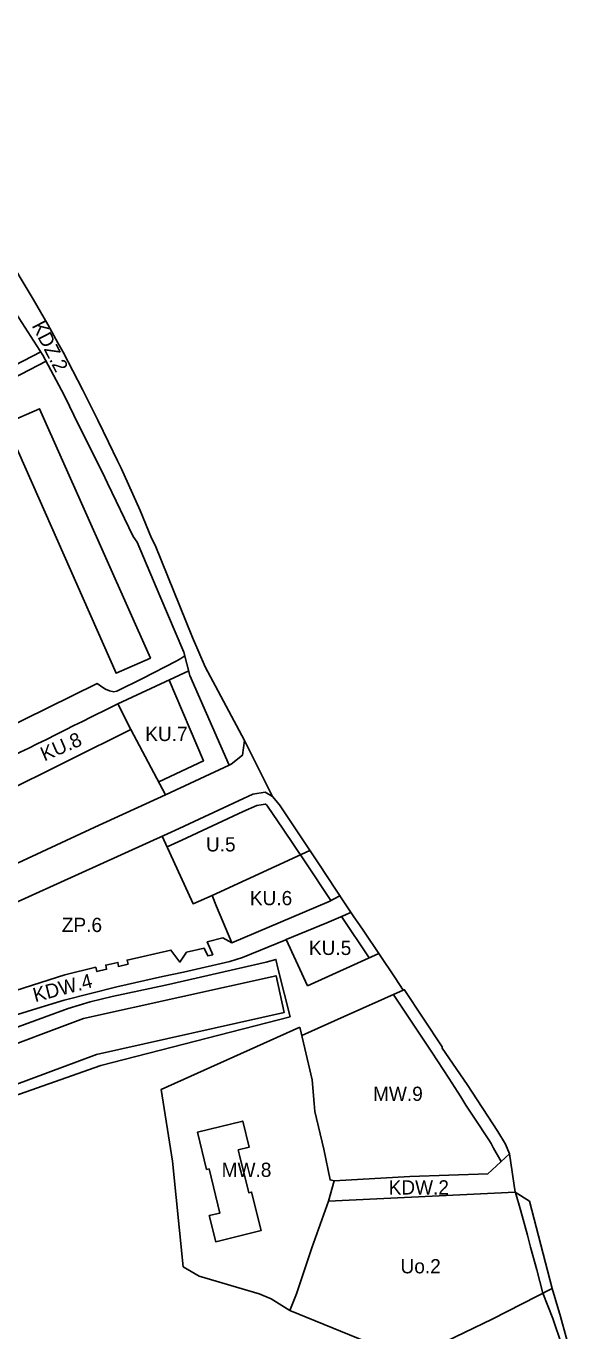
# Model space of a CAD drawing. Extents: x 7426178 to 7427732, y 5548847 to 5550287.
# Drawn here: x 7427225.9 to 7427398.2, y 5549279.8 to 5549692.3 of the extents above; entities that cross this region are included whole.
import ezdxf

# ---------------------------------------------------------------- set-up
doc = ezdxf.new("R2010")
doc.units = 0
for name, color, linetype in [('linie_rozgraniczajace', 7, 'Continuous'), ('linie_zabudowy_nieprzekraczalne', 7, 'Continuous'), ('linie_zabudowy_obowiazujace', 7, 'Continuous'), ('oznaczenia_przeznaczen', 7, 'Continuous')]:
    doc.layers.add(name, color=color, linetype=linetype)

msp = doc.modelspace()

# ---------------------------------------------------------------- linework, layer by layer
at = {"layer": 'linie_rozgraniczajace'}
for p, q in [((7427228.13, 5549605.99), (7427219.14, 5549621.01)), ((7427237.55, 5549589.21), (7427235.91, 5549592.2)), ((7427243.64, 5549577.42), (7427237.55, 5549589.21)), ((7427248.55, 5549567.8), (7427243.64, 5549577.42)), ((7427303.71, 5549448.83), (7427294.86, 5549466.52)), ((7427305.89, 5549446.11), (7427303.71, 5549448.83)), ((7427318.5, 5549427.19), (7427305.89, 5549446.11)), ((7427284.57, 5549417.53), (7427315.49, 5549431.7)), ((7427326.25, 5549415.45), (7427318.5, 5549427.19)), ((7427329.32, 5549410.72), (7427326.25, 5549415.45)), ((7427331.18, 5549408.21), (7427329.32, 5549410.72)), ((7427314.78, 5549388.92), (7427308.04, 5549403.57)), ((7427314.78, 5549388.92), (7427337.24, 5549399.15)), ((7427344.92, 5549387.57), (7427342.4, 5549391.44)), ((7427309.23, 5549379.16), (7427309.23, 5549379.16)), ((7427357.25, 5549369.27), (7427357.31, 5549369.67)), ((7427365.12, 5549357.73), (7427357.25, 5549369.27)), ((7427374.86, 5549342.9), (7427365.12, 5549357.73)), ((7427380.29, 5549323.65), (7427378.49, 5549335.83)), ((7427321.33, 5549320.9), (7427323.15, 5549327.33)), ((7427321.33, 5549320.9), (7427380.29, 5549323.65)), ((7427394.66, 5549284.38), (7427392.05, 5549293.25)), ((7427398.23, 5549271.32), (7427394.66, 5549284.38))]:
    msp.add_line(p, q, dxfattribs=at)
for points in [[(7427172.45, 5549692.34), (7427176.9, 5549682.64), (7427185.66, 5549667.5), (7427192.62, 5549654.65), (7427196.91, 5549647.34), (7427207.1, 5549629.09), (7427213.58, 5549617.58), (7427221.64, 5549603.03), (7427231.15, 5549588.29), (7427237.07, 5549577.28), (7427238.15, 5549575.04), (7427242.34, 5549566.53), (7427249.94, 5549551.24), (7427251.6, 5549547.85), (7427259.67, 5549530.97), (7427260.96, 5549529.16), (7427268.09, 5549512.22), (7427275.65, 5549494.4), (7427277.61, 5549486.99), (7427289.94, 5549458.65)], [(7427230.48, 5549589.38), (7427148.85, 5549546.95), (7427088.25, 5549515.33), (7427086.86, 5549515.01), (7427085.02, 5549515.09), (7427083.04, 5549515.77), (7427081.79, 5549516.82), (7427081.29, 5549518.09), (7427073.92, 5549541.54), (7427073.78, 5549545.19), (7427074.5, 5549552.91), (7427080.17, 5549602.79), (7427080.47, 5549609.99), (7427078.8, 5549622.63), (7427076.71, 5549630.64), (7427074.28, 5549638.8)], [(7427235.91, 5549592.2), (7427232.71, 5549598.04), (7427228.13, 5549605.99)], [(7427115.22, 5549413.02), (7427108.83, 5549432.27), (7427108.83, 5549432.27), (7427092.63, 5549482.16), (7427086.13, 5549502.57), (7427086.04, 5549505.04), (7427086.55, 5549507.51), (7427087.93, 5549510.29), (7427089.87, 5549512.02), (7427150.51, 5549543.92), (7427232.16, 5549586.41)], [(7427254.76, 5549554.9), (7427251.91, 5549560.81), (7427248.55, 5549567.8)], [(7427266.6, 5549528.2), (7427265.5, 5549530.5), (7427261.87, 5549539.15), (7427255.84, 5549552.59), (7427254.76, 5549554.9)], [(7427294.86, 5549466.52), (7427282.38, 5549489.77), (7427278.39, 5549499.07), (7427266.6, 5549528.2)], [(7427217.26, 5549469.25), (7427248.33, 5549484.49), (7427250.12, 5549483.21), (7427250.95, 5549482.7), (7427252.21, 5549482.24), (7427253.54, 5549481.92), (7427254.54, 5549482.05), (7427262.59, 5549486.08), (7427273.25, 5549491.52), (7427274.75, 5549492.36), (7427275.95, 5549493.25)], [(7427294.86, 5549466.52), (7427294.18, 5549461.82), (7427290.62, 5549458.96), (7427289.94, 5549458.65), (7427269.86, 5549449.36), (7427258.91, 5549469.96), (7427254.85, 5549478.08), (7427277.21, 5549488.48)], [(7427254.85, 5549478.08), (7427251.88, 5549476.6), (7427246.33, 5549473.85), (7427243.64, 5549472.52), (7427240.95, 5549471.19), (7427238.26, 5549469.86), (7427235.39, 5549468.41), (7427232.25, 5549466.85), (7427229.34, 5549465.41), (7427226.67, 5549464.08), (7427223.99, 5549462.75), (7427221.31, 5549461.42), (7427218.63, 5549460.09), (7427215.71, 5549458.63)], [(7427258.91, 5549469.96), (7427239.47, 5549460.24), (7427236.31, 5549458.73), (7427219.73, 5549450.51), (7427215.71, 5549458.63)], [(7427270.54, 5549437.01), (7427274.23, 5549438.66), (7427292.9, 5549447.39), (7427297.47, 5549449.53), (7427301.41, 5549450.12), (7427303.71, 5549448.83)], [(7427172.51, 5549404.3), (7427192.72, 5549413.62), (7427247.52, 5549439.05), (7427269.86, 5549449.36)], [(7427191.99, 5549400.58), (7427193.09, 5549401.11), (7427192.87, 5549401.78), (7427270.54, 5549437.01)], [(7427268.84, 5549436.24), (7427278.59, 5549414.89), (7427284.57, 5549417.53), (7427285.94, 5549414.03), (7427290.85, 5549402.55), (7427288.04, 5549404.1), (7427283.09, 5549402.88), (7427284.81, 5549398.78), (7427283.21, 5549398.43), (7427282.09, 5549400.85), (7427276.53, 5549399.56), (7427274.41, 5549396.43), (7427271.57, 5549400.22), (7427257.74, 5549397.06), (7427258.05, 5549395.78), (7427255, 5549395.07), (7427254.86, 5549396.34), (7427251.01, 5549395.48), (7427251.26, 5549394.16), (7427248.21, 5549393.43), (7427247.83, 5549394.81), (7427238.13, 5549392.37), (7427214.65, 5549384.89)], [(7427290.85, 5549402.55), (7427321.54, 5549415.63), (7427324.98, 5549417.38)], [(7427307.84, 5549403.48), (7427308.04, 5549403.57), (7427320.84, 5549408.89), (7427326.75, 5549411.42), (7427328.1, 5549411.99), (7427328.43, 5549412.09)], [(7427342.4, 5549391.44), (7427332.51, 5549406.21), (7427331.18, 5549408.21)], [(7427307.84, 5549403.48), (7427294.24, 5549397.88), (7427290.18, 5549396.65), (7427275.57, 5549393.25), (7427268.93, 5549391.83), (7427254.5, 5549388.59), (7427237.89, 5549384.43), (7427229.28, 5549381.76), (7427206.45, 5549374.66), (7427194.14, 5549397.18)], [(7427208.1, 5549370.51), (7427214.58, 5549372.79), (7427231.65, 5549379.05), (7427239.19, 5549381.81), (7427246.05, 5549383.91), (7427253.06, 5549385.54), (7427269.91, 5549389.18), (7427301.72, 5549396.43), (7427304.78, 5549397.3), (7427305.44, 5549394.04)], [(7427309.23, 5549379.16), (7427305.44, 5549394.04)], [(7427312.9, 5549373.19), (7427326.3, 5549379.21), (7427344.92, 5549387.57)], [(7427357.31, 5549369.67), (7427345.31, 5549387.76), (7427344.92, 5549387.57)], [(7427111.3, 5549275.29), (7427112.42, 5549276.71), (7427113.63, 5549278.4), (7427115.63, 5549280.17), (7427121.01, 5549284.98), (7427123.37, 5549287.21), (7427128.8, 5549292.12), (7427130.82, 5549293.83), (7427131.43, 5549294.45), (7427134.33, 5549296.6), (7427143.02, 5549303.88), (7427149.6, 5549309.36), (7427153.81, 5549312.46), (7427154.8, 5549315.39), (7427150.02, 5549327.69), (7427166.15, 5549333.81), (7427181.85, 5549339.96), (7427249.51, 5549363.69), (7427309.23, 5549379.16)], [(7427312.27, 5549375.84), (7427268.48, 5549356.11), (7427272.09, 5549333.51), (7427275.43, 5549300.14), (7427280.48, 5549297.11), (7427299.44, 5549291.54), (7427303.23, 5549289.96), (7427309.2, 5549286.26)], [(7427378.49, 5549335.83), (7427371.65, 5549329.53), (7427347.01, 5549328.6), (7427323.15, 5549327.33), (7427321.87, 5549327.59), (7427319.84, 5549337.32), (7427317, 5549349.15), (7427316.88, 5549351.71), (7427316.21, 5549359.24), (7427312.27, 5549375.84)], [(7427378.49, 5549335.83), (7427377.23, 5549338.89), (7427374.86, 5549342.9)], [(7427392.05, 5549293.25), (7427384.84, 5549320.85), (7427380.29, 5549323.65)], [(7427309.2, 5549286.26), (7427311.3, 5549291.52), (7427316.14, 5549306.06), (7427321.33, 5549320.9)], [(7427309.2, 5549286.26), (7427346.86, 5549270.85), (7427373.04, 5549283.57), (7427392.05, 5549293.25)]]:
    msp.add_lwpolyline(points, dxfattribs=at)
at = {"layer": 'linie_zabudowy_nieprzekraczalne'}
for points in [[(7427267.81, 5549453.42), (7427281.86, 5549460.03), (7427271, 5549485.59)], [(7427298.7, 5549445.92), (7427294.45, 5549443.99), (7427275.06, 5549435.03), (7427270.37, 5549432.88)], [(7427322.09, 5549415.91), (7427314, 5549428.1), (7427307.01, 5549438.42), (7427302.06, 5549445.78), (7427301.82, 5549446.12), (7427301.71, 5549446.24), (7427301.61, 5549446.32), (7427301.36, 5549446.31), (7427300.1, 5549446.18), (7427298.7, 5549445.92)], [(7427334.16, 5549397.74), (7427325.44, 5549410.86)], [(7427375.85, 5549333.39), (7427373.51, 5549337.63), (7427372.77, 5549339.1), (7427372.05, 5549340.2), (7427367.45, 5549347.14), (7427364.77, 5549351.24), (7427363.17, 5549353.87), (7427359.34, 5549359.71), (7427353.97, 5549367.91), (7427349.13, 5549375.2), (7427342.03, 5549385.94)], [(7427389.05, 5549291.73), (7427387.15, 5549299.17), (7427385.19, 5549306.34), (7427384.17, 5549310.12), (7427382.04, 5549318.1), (7427380.43, 5549323.56)], [(7427397.24, 5549237.81), (7427397.08, 5549245.31), (7427396.9, 5549250.32), (7427396.71, 5549253.09), (7427396.41, 5549258.41), (7427395.04, 5549275.33), (7427392.19, 5549283.75), (7427389.09, 5549291.74)]]:
    msp.add_lwpolyline(points, dxfattribs=at)
at = {"layer": 'linie_zabudowy_obowiazujace'}
for points in [[(7427219.41, 5549566.73), (7427254.28, 5549487.73), (7427265.14, 5549492.55), (7427230.12, 5549571.35), (7427219.41, 5549566.73)], [(7427244.03, 5549378.6), (7427151.37, 5549343.86), (7427155.52, 5549332.77), (7427248.12, 5549367.2), (7427307.4, 5549380.55), (7427304.83, 5549392.09), (7427244.03, 5549378.6)], [(7427292.86, 5549337.04), (7427296.3, 5549337.88), (7427294.27, 5549346.17), (7427279.96, 5549342.66), (7427282.85, 5549330.87), (7427283.64, 5549331.07), (7427287.07, 5549317.11), (7427283.71, 5549316.29), (7427285.73, 5549308.04), (7427300.06, 5549311.56), (7427297.08, 5549323.71), (7427296.18, 5549323.49), (7427293.27, 5549335.37), (7427292.86, 5549337.04)]]:
    msp.add_lwpolyline(points, dxfattribs=at)

# ---------------------------------------------------------------- texts
at = {"layer": 'oznaczenia_przeznaczen'}
for s, rotation, p in [('KDZ.2', 297.2411, (7427227.53, 5549597.66)), ('KU.8', 23.3696, (7427231.62, 5549459.84)), ('KDW.4', 14.5641, (7427228.7, 5549383.74))]:
    msp.add_text(s, height=4.5, rotation=rotation, dxfattribs=at).set_placement(p)
for s, p in [('KU.7', (7427263.48, 5549466.31)), ('U.5', (7427282.66, 5549431.41)), ('KU.6', (7427296.52, 5549414.42)), ('ZP.6', (7427237.14, 5549405.94)), ('KU.5', (7427315.18, 5549398.68)), ('MW.9', (7427335.43, 5549352.55)), ('MW.8', (7427287.62, 5549328.52)), ('KDW.2', (7427340.35, 5549322.96)), ('Uo.2', (7427344.11, 5549298.03))]:
    msp.add_text(s, height=4.5, dxfattribs=at).set_placement(p)

doc.saveas('drawing.dxf')
